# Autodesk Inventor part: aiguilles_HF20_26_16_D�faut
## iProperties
Created: 2011-01
Part Number: aiguilles_HF20_26_16_D�faut
Document SubType Name: Modeling
Designer: eric
Density: 1 g/cm^3
Mass: 0.0437477 g
Surface Area: 0.926714 cm^2
Volume: 0.0437477 cm^3
Author: eric
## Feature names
1. Base1
